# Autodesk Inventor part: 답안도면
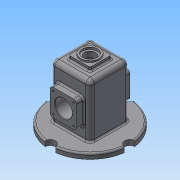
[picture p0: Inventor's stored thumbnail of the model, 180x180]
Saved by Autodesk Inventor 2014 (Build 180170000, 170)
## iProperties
Created: 2018-07
Part Number: 답안도면
Material: 일반
Document SubType Name: Modeling
Designer: 학생용
Density: 1 g/cm^3
Appearance: 기본값
Author: 학생용
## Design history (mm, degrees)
sketch "스케치2"
  geometry: L1 (37, -55)-(-37, -55); L2 (-37, -55)-(-37, 55); L3 (-37, 55)-(37, 55); L4 (37, 55)-(37, -55); L5 (37, -55)-(-37, 55); L6 (-37, -55)-(37, 55); 1 further point
  constraints: 12 end point, 2 midpoint, 2 parallel, 1 horizontal, 1 perpendicular
  dimensions: "d0" = 74 distance of L2.end L3.end; "d1" = 110 distance of L3.end L1.start
extrude "돌출1" new body sketch "스케치2" stored distance "d2" = 74; taper "d3" = 0 deg
feature "쉘1" dims "d6" = 5
fillet "모깎기1" dims "d7" = 8
fillet "모깎기2" dims "d13" = 8
sketch "스케치5"
  geometry: L1 (-37, -55)-(-37, 47) reference; L2 (-32, 50)-(-32, -55) reference; L3 (32, -55)-(32, 50) reference; L4 (37, 47)-(37, -55) reference; L5 (32, -55)-(-32, -55) reference; L6 (-37, 0)-(37, 0); L7 (-32, 25)-(-25, 22.452); L8 (-25, 22.452)-(-25, 0); L9 (-32, 25)-(-32, 0); 1 further point
  constraints: 8 end point, 6 point on line, 2 perpendicular
  dimensions: "d14" = 55 distance between parallel lines of L5 L6; "d15" = 7 distance between parallel lines of L2 L8; "d16" = 110 deg angle of L8 L7; "d17" = 50 diameter of L7.start L6
revolve "회전1" sketch "스케치5" stored, may be unused: angle "d18" = 90 deg
node "작업 평면1"
sketch "스케치6"
  geometry: L1 (-25, -25)-(25, -25); L2 (25, -25)-(25, 25); L3 (25, 25)-(-25, 25); L4 (-25, 25)-(-25, -25); L5 (-25, -25)-(25, 25); L6 (25, -25)-(-25, 25); 1 further point
  constraints: 12 end point, 2 midpoint, 2 parallel, 1 horizontal, 1 perpendicular
  dimensions: "d20" = 50 distance of L2.end L3.end; "d21" = 50 distance of L1.end L2.end
extrude "돌출2" join sketch "스케치6" stored distance "d22" = 100; taper "d23" = 0 deg
fillet "모깎기3" dims "d24" = 6
sketch "스케치8"
  geometry: C1 r 16 at (19, 25); 1 further point
  constraints: 1 centre point, 1 coincident
  dimensions: "d26" = 32 diameter of C1
extrude "돌출3" cut sketch "스케치8" stored distance "d27" = 100; taper "d28" = 0 deg
fillet "모깎기4" dims "d29" = 3
fillet "모깎기5" dims "d30" = 3
sketch "스케치10"
  geometry: L1 (9, 9)-(49, 9); L2 (49, 9)-(49, 49); L3 (49, 49)-(9, 49); L4 (9, 49)-(9, 9); L5 (9, 9)-(49, 49); L6 (49, 9)-(9, 49); 1 further point
  constraints: 12 end point, 2 midpoint, 2 parallel, 1 horizontal, 1 perpendicular
  dimensions: "d32" = 40 distance of L2.end L3.end; "d33" = 40 distance of L3.end L1.start
extrude "돌출4" join sketch "스케치10" distance "d34" = 7; taper "d35" = 0 deg
sketch "스케치11"
  geometry: C1 r 17.5 at (29, 29); 1 further point
  constraints: 1 centre point, 1 coincident
  dimensions: "d37" = 35 diameter of C1
extrude "돌출5" join sketch "스케치11" distance "d38" = 3; taper "d39" = 0 deg
sketch "스케치12"
  geometry: C1 r 17.5 at (0, 0) reference; C2 r 14 at (0, 0)
  constraints: 1 centre point, 1 coincident
  dimensions: "d40" = 28 diameter of C2
extrude "돌출6" cut sketch "스케치12" distance "d41" = 4; taper "d42" = 0 deg
sketch "스케치13"
  geometry: C1 r 14 at (0, 0) reference; C2 r 10.5 at (0, 0)
  constraints: 1 centre point, 1 coincident
  dimensions: "d43" = 21 diameter of C2
extrude "돌출7" cut sketch "스케치13" stored distance "d44" = 4; taper "d45" = 0 deg
sketch "스케치14"
  geometry: L1 (-8, 66)-(-8, 8) reference; L2 (58, 0)-(0, 0) reference; L3 (66, 8)-(66, 66) reference; L4 (0, 74)-(58, 74) reference; C1 r 75 at (29, 37); A1 r 8 centre (0, 66) between (0, 74) and (-8, 66) reference; A2 r 8 centre (0, 8) between (-8, 8) and (0, 0) reference; A3 r 8 centre (58, 8) between (58, 0) and (66, 8) reference; A4 r 8 centre (58, 66) between (66, 66) and (58, 74) reference; 1 further point
  constraints: 1 centre point, 1 coincident
  dimensions: "d46" = 150 diameter of C1
extrude "돌출8" join sketch "스케치14" distance "d47" = 10; taper "d48" = 0 deg
sketch "스케치16"
  geometry: A1 r 6 centre (0, 44) between (0, 50) and (-6, 44) reference; A2 r 6 centre (0, 6) between (-6, 6) and (0, 0) reference; A3 r 6 centre (38, 6) between (38, 0) and (44, 6) reference; A4 r 6 centre (38, 44) between (44, 44) and (38, 50) reference; 4 further points
  constraints: 4 coincident
hole "구멍1" sketch "스케치16" at (0, 44), (38, 44), (38, 6), (0, 6) diameter "d62" = 3.242; stored, may be unused: countersink angle "d66" = 90 deg, drill point angle "d68" = 118 deg; dims "d63" = 8, "d64" = 4, "d65" = 2, "d67" = 10
fillet "모깎기7" dims "d69" = 3
fillet "모깎기8" dims "d70" = 3
sketch "스케치17"
  geometry: L1 (-40, 29)-(-40, -29) reference; L2 (0, 0)-(0, 75); C1 r 10 at (0, 75)
  constraints: 2 end point, 1 centre point, 1 coincident, 1 parallel, 1 vertical alignment, 1 other
  dimensions: "d72" = 10 radius of C1
extrude "돌출10" cut sketch "스케치17" distance "d73" = 10; taper "d74" = 0 deg
fillet "모깎기9" dims "d78" = 3
fillet "모깎기10" dims "d79" = 3
fillet "모깎기11" dims "d80" = 3
chamfer "모따기1" distance "d81" = 1; stored, may be unused: second distance "d82" = 2, angle "d83" = 45 deg
sketch "스케치19"
  geometry: L1 (-37, 42)-(-37, -47) reference; L2 (-74.333, 55)-(-9.978, 55) reference; L3 (-17.5, -65)-(17.5, -65) reference; 2 further points
  constraints: 1 other
  dimensions: "d84" = 37 distance from line of L1 point (0, -35); "d85" = 30 distance from line of L3 point (0, -35)
feature "엠보싱1" sketch "스케치19" dims "d0" = 74, "d1" = 110, "d86" = 0.5, "d87" = 0
node "솔리드1"
mirror "대칭1"
mirror "대칭2"
mirror "대칭3"
pattern_circular "원형 패턴2" dims angle "d76" = 360 deg
